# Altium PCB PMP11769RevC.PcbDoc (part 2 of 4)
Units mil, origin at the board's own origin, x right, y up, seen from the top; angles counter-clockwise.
Board outline 7800 x 8510 mil, 4 copper layers (Top, Inner Top, Inner Bottom, Bottom), stack 33.235 mil thick; 451 components, 226 nets, 1199 pads, 1742 vias.
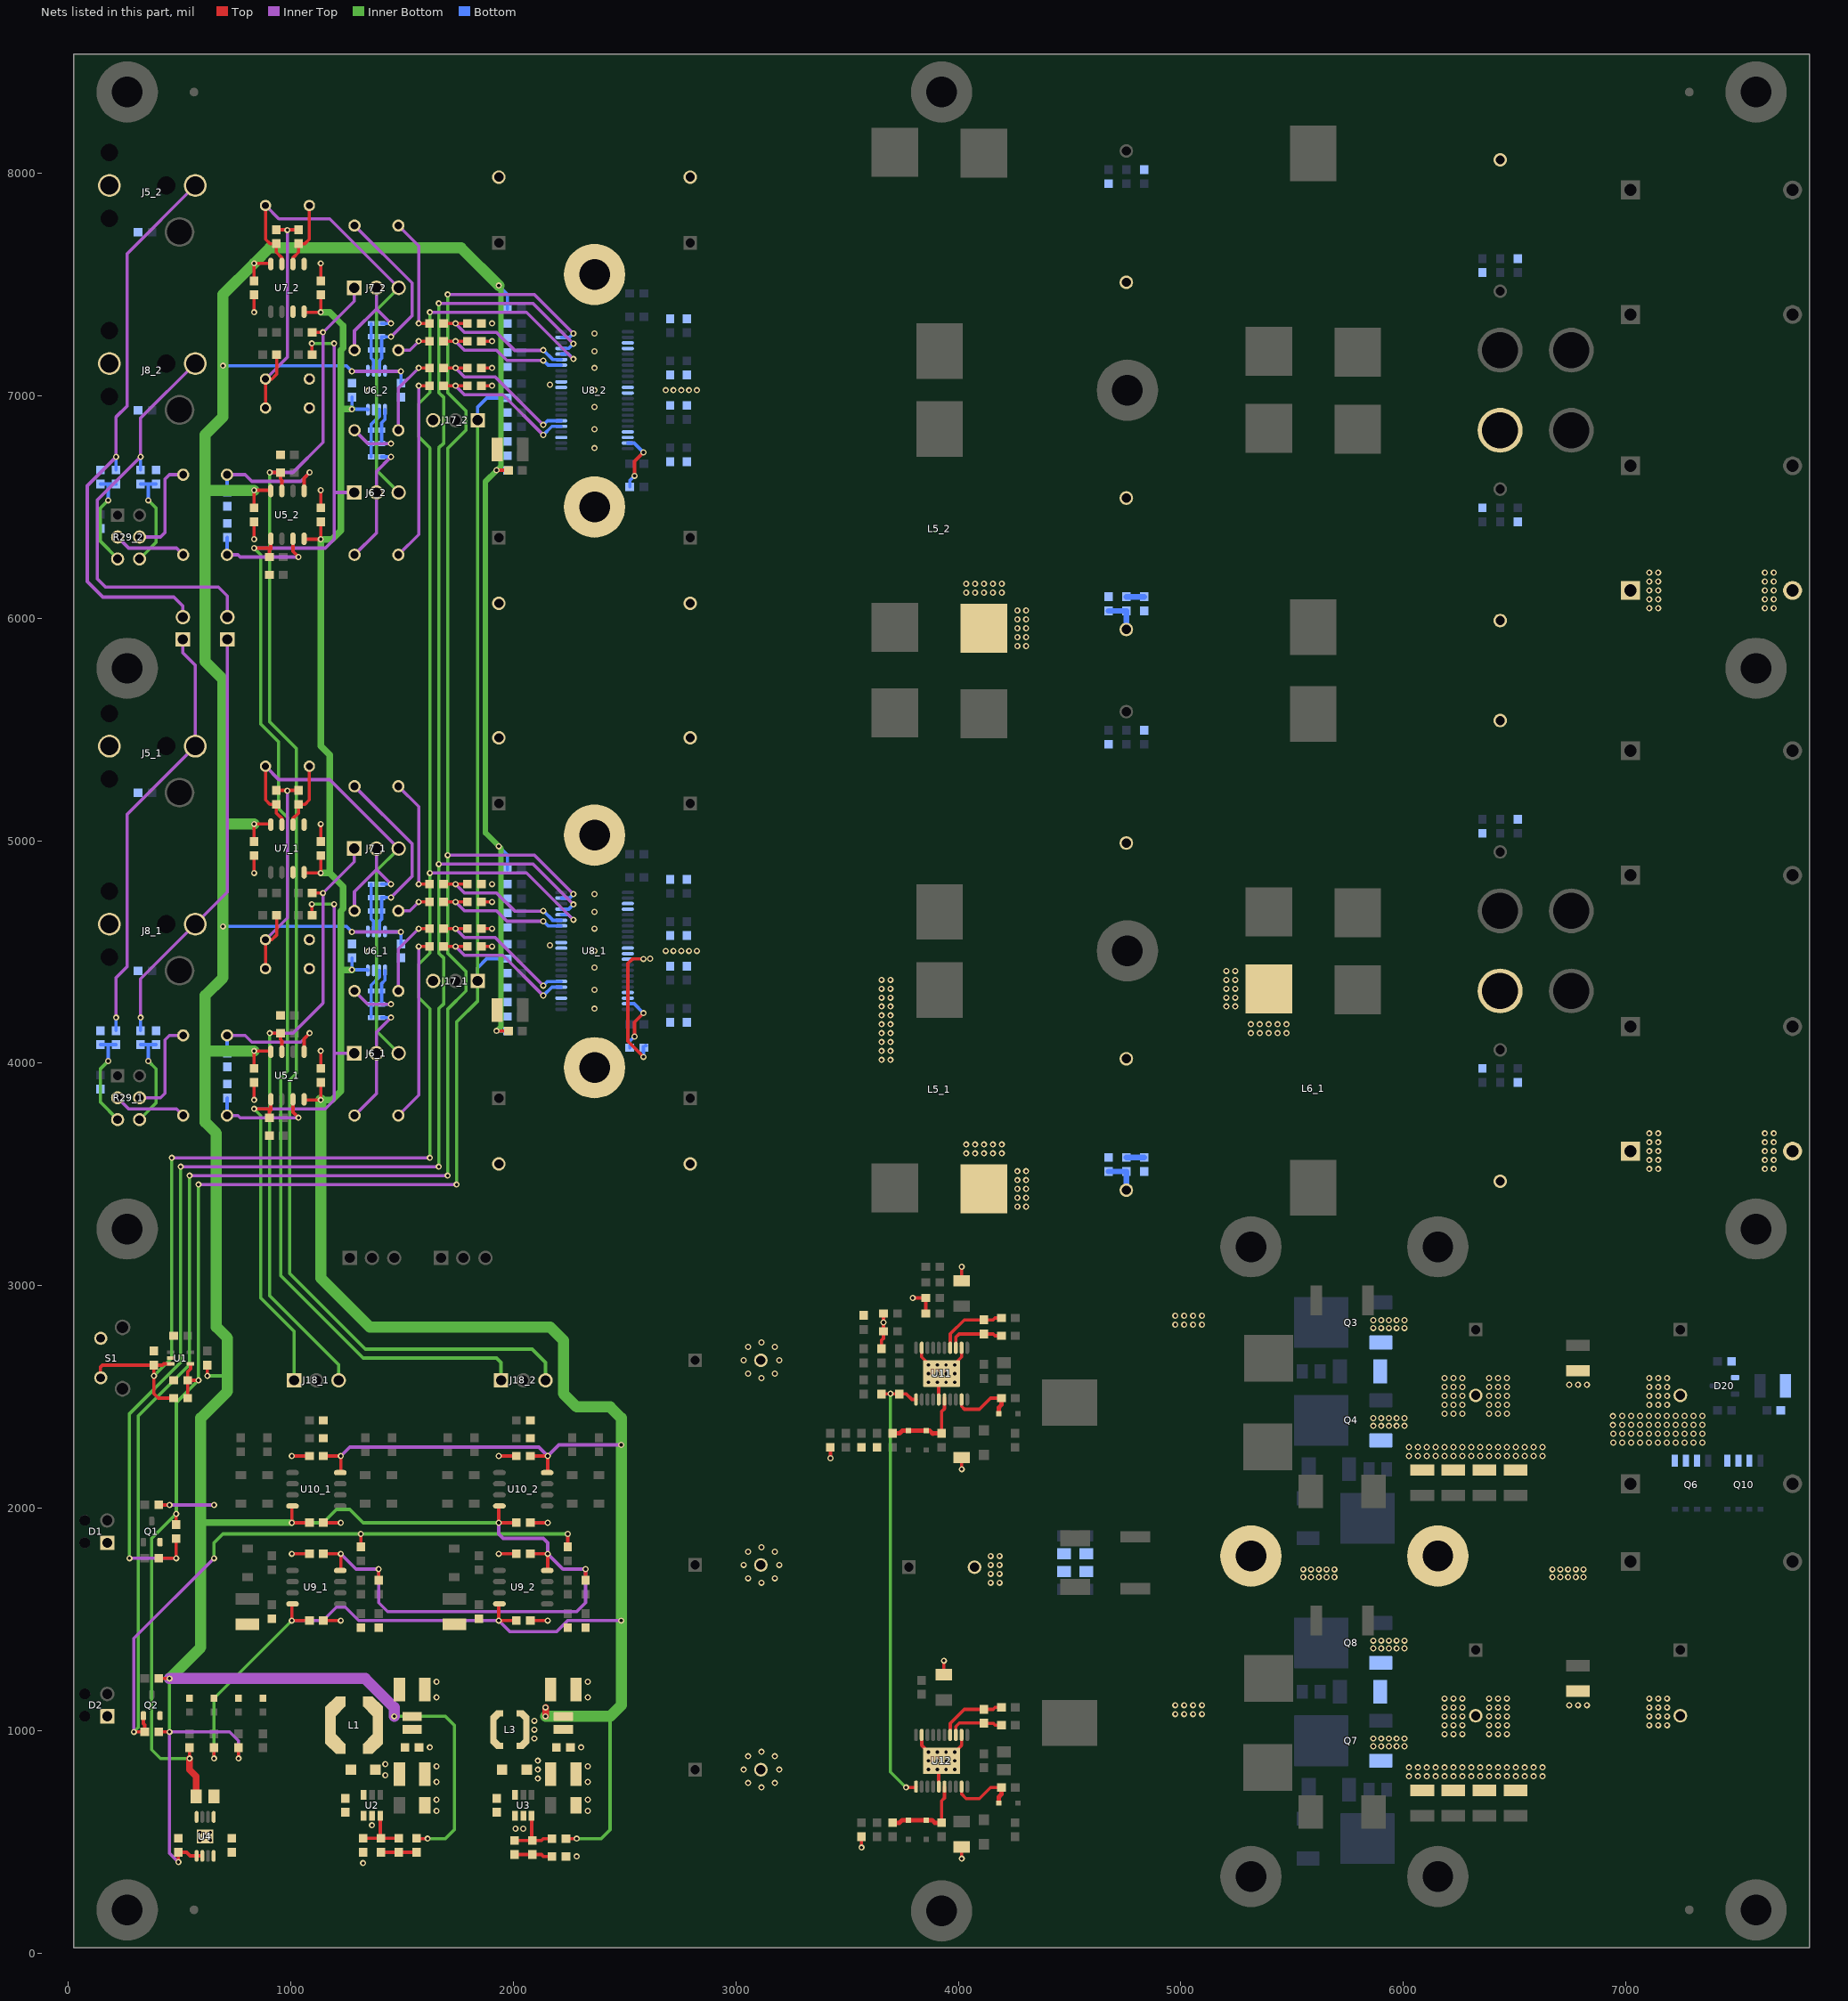
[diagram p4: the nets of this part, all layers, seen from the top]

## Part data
C1 C14 C58_1 C58_2 C59_1 C59_2 C71_1 C71_2: "CAP, CERM, 1 µF, 25 V, +/- 10%, X7R, 0603"
C2 C3 C7 C9 C12 C19_1 C19_2 C23_1 C23_2 C26_1 C26_2 C29_1 C29_2 C30_1 C30_2 C36_1 C36_2 C60_1 C60_2 C66_1 C66_2 C72_1 C72_2 C73_1 C73_2 C77_1 C77_2 C78_1 C78_2 C80_1 C80_2 C81_1 C81_2 C82_1 C82_2 C104 C106: "CAP, CERM, 0.1 µF, 50 V, +/- 10%, X7R, 0603"
C4 C13 C92 C93: "CAP, CERM, 1 µF, 50 V, +/- 10%, X7R, 1206"
C5 C6 C10 C11 C67_1 C67_2 C79_1 C79_2: "CAP, CERM, 10 µF, 25 V, +/- 20%, X7R, 1210"
C8 C17: "CAP, CERM, 220 pF, 50 V, +/- 5%, C0G/NP0, 0603"
C15: "CAP, CERM, 4.7 µF, 10 V, +/- 20%, X7R, 0805"
C16 C90: "CAP, CERM, 1000 pF, 50 V, +/- 10%, X7R, 0603"
C18_1 C18_2 C22_1 C22_2 C25_1 C25_2 C32_1 C32_2 C35_1 C35_2 C39_1 C39_2: "CAP, Film, 4.7 µF, 50 V, +/- 5%, TH"
C20_1 C20_2 C31_1 C31_2: "CAP, CERM, 22 pF, 50 V, +/- 5%, C0G/NP0, 0402"
C21_1 C21_2 C24_1 C24_2 C28_1 C28_2 C37_1 C37_2 C38_1 C38_2 C40_1 C40_2 C91: "CAP, CERM, 100 pF, 50 V, +/- 5%, C0G/NP0, 0603"
C27_1 C27_2: "CAP, Film, 0.1 µF, 63 V, +/- 5%, TH"
C33_1 C33_2: "CAP, Film, 0.22 µF, 63 V, +/- 5%, TH"
C34_1 C34_2: "CAP, Film, 0.15 µF, 63 V, +/- 5%, TH"
C41_1 C41_2 C61_1 C61_2 C68_1 C68_2 C74_1 C74_2: "CAP, CERM, 0.01 µF, 50 V, +/- 10%, X7R, 0603"
C42_1 C42_2 C43_1 C43_2 C44_1 C44_2 C45_1 C45_2 C109 C110 C113 C114: "CAP, AL, 820 µF, 50 V, +/- 20%, 0.042 ohm, TH"
C46_1 C46_2 C47_1 C47_2 C48_1 C48_2 C49_1 C49_2 C50_1 C50_2 C51_1 C51_2 C52_1 C52_2 C53_1 C53_2: "CAP, CERM, 1 µF, 50 V, +/- 10%, X7R, 0603"
C54_1 C54_2 C55_1 C55_2 C64_1 C64_2 C65_1 C65_2: "CAP, CERM, 0.033 µF, 50 V, +/- 10%, X7R, 0603"
C56_1 C56_2 C62_1 C62_2 C69_1 C69_2 C75_1 C75_2: "CAP, Film, 1 µF, 250 V, +/- 5%, TH"
C57_1 C57_2 C63_1 C63_2 C70_1 C70_2 C76_1 C76_2: "CAP, CERM, 1000 pF, 100 V, +/- 5%, C0G/NP0, 0603"
C83 C84: "CAP, CERM, 220 pF, 50 V, +/- 10%, X7R, 0603"
C85: "CAP, CERM, 0.047 µF, 50 V, +/- 10%, X7R, 0603"
C86 C87: "CAP, CERM, 4.7 µF, 16 V, +/- 20%, X7R, 1206"
C88 C89: "CAP, CERM, 0.22 µF, 25 V, +/- 10%, X7R, 0805"
C94: "CAP, CERM, 2.2 µF, 6.3 V, +/- 10%, X7R, AEC-Q200 Grade 1, 0603"
C95 C96 C111 C112 C115 C116: "CAP, CERM, 1000 pF, 100 V, +/- 20%, X7R, 0805"
C97 C99 C100 C102 C103 C105 C117 C119 C120 C122 C123: library part C3225X7R1H335M, "CAP, CERM, 4.7 µF, 50 V, +/- 15%, X7R, 1210"
C98 C101 C118 C121: "CAP, AL, 1800 µF, 35 V, +/- 20%, 0.028 ohm, TH"
C107 C108: "CAP, CERM, 0.1 µF, 100 V, +/- 10%, X7R, 0805"
D1 D2: library part 551-0403F, "LED, Yellow, TH"
D3 D8 D14 D15: library part PMEG6010CEH,115, "Diode, Schottky, 60 V, 1 A, SOD-123F"
D4 D5 D6 D7: "LED, Green, SMD"
D9_1 D9_2 D10_1 D10_2 D11_1 D11_2 D12_1 D12_2 D13_1 D13_2: library part 1N4148WFL-G3-08, "Diode, Switching, 100 V, 0.15 A, SOD-123FL"
D16 D21: library part SS36-E3/57T, "Diode, Schottky, 60 V, 3 A, SMC"
D17 D18 D19 D22 D23 D24: library part BAT54HT1G, "Diode, Schottky, 30 V, 0.2 A, SOD-323"
D20: "Diode, Zener, 15 V, 225 mW, SOT-23"
FID1 FID2 FID3 FID4: "Fiducial mark.  There is nothing to buy or mount."
J1 J3: "Header, 2.54 mm, 2x1, Gold, TH"
J2 J4 J6_1 J6_2 J7_1 J7_2 J17_1 J17_2 J18_1 J18_2: "Header, 2.54 mm, 3x1, Gold, TH"
J5_1 J5_2: "RCA Jack, Red, R/A, TH"
J8_1 J8_2: "RCA Jack, Black, R/A, TH"
J9_1 J9_2 J13_1 J13_2 J19: library part "973 582-101", "TEST SOCKET, PCB, 4MM, RED"
J10_1 J10_2 J11_1 J11_2 J14_1 J14_2 J15_1 J15_2: library part H3492-01, "Pin Receptacle, Dia 4 mm, Gold, TH"
J12_1 J12_2 J16_1 J16_2 J20: library part "973 582-100", "TEST SOCKET, PCB, 4MM, BLACK"
L1: "Inductor, Shielded Drum Core, Ferrite, 330 µH, 0.3 A, 1.2 ohm, SMD"
L2 L4: "Inductor, Shielded, Composite, 500 nH, 2.3 A, 0.04 ohm, SMD"
L3: "Inductor, Shielded Drum Core, Ferrite, 1 mH, 0.1 A, 21.5 ohm, SMD"
L5_1 L5_2 L6_1 L6_2 L7_1 L7_2 L8_1 L8_2 L9 L11: "Inductor, Shielded E Core, Ferrite, 10 µH, 28 A, 0.0026 ohm, SMD"
L10: library part IHLP2525AHERR10M01, "Inductor, Shielded, Ferrite, 100 nH, 18 A, 0.0035 ohm, SMD"
Q1 Q2: library part 2N7002E-T1-E3, "MOSFET, N-CH, 60 V, 0.24 A, SOT-23"
Q3 Q4 Q5 Q7 Q8 Q9: library part SUD50N10-18P, "MOSFET, N-CH, 60 V, 50 A, DPAK"
Q6 Q10: "MOSFET, N-CH, 30 V, 51 A, SON 5x6mm"
R1 R7: "RES, 47.5 k, 1%, 0.1 W, 0603"
R2 R8: "RES, 3.32 k, 1%, 0.1 W, 0603"
R3 R6 R25_1 R25_2 R30_1 R30_2 R43_1 R43_2 R53_1 R53_2 R55_1 R55_2 R56_1 R56_2 R59_1 R59_2 R61_1 R61_2 R63_1 R63_2 R64_1 R64_2 R65_1 R65_2 R66_1 R66_2: "RES, 10.0 k, 1%, 0.1 W, 0603"
R4 R19_1 R19_2 R20_1 R20_2 R26_1 R26_2 R36_1 R36_2 R37_1 R37_2 R42_1 R42_2: "RES, 100, 1%, 0.1 W, 0603"
R5: "RES, 80.6 k, 1%, 0.1 W, 0603"
R9 R17 R77: "RES, 49.9, 1%, 0.1 W, 0603"
R10 R16 R58_1 R58_2 R89 R91 R92 R100 R101: "RES, 1.00 k, 1%, 0.1 W, 0603"
R11 R18: "RES, 14.7 k, 1%, 0.1 W, 0603"
R12: "RES, 11.0 k, 1%, 0.1 W, 0603"
R13 R14: "RES, 2.94 k, 1%, 0.1 W, 0603"
R15: "RES, 200, 1%, 0.1 W, 0603"
R21_1 R21_2 R27_1 R27_2 R38_1 R38_2 R39_1 R39_2: "RES, 10.0 k, 1%, 0.063 W, 0402"
R22_1 R22_2: "RES, 13.7 k, 1%, 0.1 W, 0603"
R23_1 R23_2 R32_1 R32_2 R40_1 R40_2 R54_1 R54_2 R67 R70 R72 R73 R75 R76 R79 R83: "RES, 0, 5%, 0.1 W, 0603"
R24_1 R24_2 R41_1 R41_2 R74 R78: "RES, 100 k, 1%, 0.1 W, 0603"
R28_1 R28_2 R33_1 R33_2 R81 R84: "RES, 20.0 k, 1%, 0.1 W, 0603"
R29_1 R29_2: "Trimmer Potentiometer, 10K Ohm, 0.025W, TH"
R31_1 R31_2 R44_1 R44_2: "RES, 24.3 k, 1%, 0.1 W, 0603"
R34_1 R34_2: "RES, 4.53 k, 1%, 0.1 W, 0603"
R35_1 R35_2: "RES, 6.81 k, 1%, 0.1 W, 0603"
R45_1 R45_2 R46_1 R46_2 R47_1 R47_2 R48_1 R48_2 R50_1 R50_2 R51_1 R51_2 R52_1 R52_2 R69 R71: "RES, 3.32, 1%, 0.1 W, 0603"
R49_1 R49_2: "RES, 22.1 k, 1%, 0.1 W, 0603"
R57_1 R57_2: "RES, 23.7 k, 1%, 0.1 W, 0603"
R60_1 R60_2: "RES, 200 k, 1%, 0.1 W, 0603"
R62_1 R62_2: "RES, 365 k, 1%, 0.1 W, 0603"
R68: "RES, 30.1 k, 1%, 0.1 W, 0603"
R80: "RES, 7.68 k, 1%, 0.1 W, 0603"
R82: "RES, 37.4 k, 1%, 0.1 W, 0603"
R85: "RES, 3.74 k, 1%, 0.1 W, 0603"
R86: "RES, 44.2 k, 1%, 0.1 W, 0603"
R87 R90 R97 R99: "RES, 8.2, 5%, 0.75 W, 2010"
R88 R98: "RES, 0.0015, 1%, 1 W, 2512"
R93 R94 R95 R102 R103 R104: "RES, 4.75, 1%, 0.1 W, 0603"
R96: "RES, 0.68, 5%, 1 W, 2512"
S1: library part 1825027-2, "Switch, SPST-NO, Off-Mom, 0.05 A, 12 V, R/A, TH"
U1: library part TPS3803-01QDCKRQ1, "VOLTAGE DETECTOR, DCK0005A"
U2 U3: library part LM2841XMK-ADJL, "300 mA/600 mA up to 42V Input Step-Down DC/DC Regulator, 6-pin Tiny SOT23"
U4: library part TPS7A6633QDGNRQ1, "High-Voltage Ultralow-Iq Low-Dropout Regulator, DGN0008D"
U5_1 U5_2 U7_1 U7_2: library part OPA1662AIDRQ1, "Automotive Catalog, Sound Plus, Low-Power, Low-Noise and Distortion, Audio Operational Amplifier, 3 to 36 V, -40 to 85 degC, 8-pin SOIC (D0008A), Green (RoHS & no Sb/Br)"
U6_1 U6_2: "Automotive Catalog, Sound Plus, Low-Power, Low-Noise and Distortion, Audio Operational Amplifier, 3 to 36 V, -40 to 85 degC, 8-pin SOP (DGK0008A), Green (RoHS & no Sb/Br)"
U8_1 U8_2: library part TPA3251D2DDVR, "150W Stereo/300W MONO PurePath HD Analog-input Power Stage, DDV0044D"
U9_1 U9_2 U10_1 U10_2: library part LM2904QDRQ1, "Automotive Dual Low Power Op Amp, D0008A"
U11 U12: library part LM5122QMHX/NOPB, "Wide Input Synchronous Boost Controller with Multiple Phase Capability, PWP0020A"

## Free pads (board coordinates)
  round 275.59 hole 137.8 unplated: 0(265,195) 0(265,3255) 0(265,5775) 0(265,8365) 0(3925,190) 0(3925,8365) 0(4760,4505) 0(4760,7025) 0(5315,345) 0(5315,3175) 0(6155,345) 0(6155,3175) 0(7585,195) 0(7585,3255) 0(7585,5775) 0(7585,8365)
  round 275.59 hole 137.8: 0(2365,3980) 0(2365,5025) 0(2365,6500) 0(2365,7545) 0(5315,1785) 0(6155,1785)

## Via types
v1: diameter 28, hole 15, Top to Bottom, 1742 vias

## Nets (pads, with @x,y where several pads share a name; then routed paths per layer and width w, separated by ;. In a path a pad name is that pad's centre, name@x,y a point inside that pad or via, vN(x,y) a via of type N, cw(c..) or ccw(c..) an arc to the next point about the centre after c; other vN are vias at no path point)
+3V3: C2.2 C15.1 J17_1.1 J17_2.1 R1.2 R3.2 R15.2 R54_1.1 R54_2.1 U1.4 U4.8 | length 8355.1
  Top w15: R1.2@485,1926.5 v1(485,1975) ; R3.2@536.5,2495 C2.2@536.5,2575 ; v1(545,875) R15.2@545,923.5 ; U1.4@549.29,2649.41 549.29,2626.14 536.5,2613.35 C2.2@536.5,2575 ; v1(585,2575) C2.2@536.5,2575
  Top w30: v1(545,875) 545,825 575,795 C15.1@575,705
  Inner Top w15: v1(585,3455) v1(1745,3455)
  Inner Bottom w15: v1(545,875) 415,875 375,915 375,1865 v1(485,1975) 485.37,1975.37 485.37,2475.37 v1(585,2575) v1(585,3455) ; v1(1745,3455) 1745,4185 1840,4280 J17_1.1@1840,4370 J17_2.1@1840,6890
  Bottom w15: J17_1.1@1840,4370 1840,4429.49 1880.51,4470 R54_1.1@1973.5,4470 ; J17_2.1@1840,6890 1840,6949.49 1880.51,6990 R54_2.1@1973.5,6990
+12V: C6.1 C14.1 C23_1.1 C23_2.1 C26_1.1 C26_2.1 C29_1.1 C29_2.1 C77_1.1 C77_2.1 C78_1.1 C78_2.1 L2.2 R2.2 R5.2 R7.2 R8.2 R9.2 R13.2 R46_1.2 R46_2.2 R48_1.2 R48_2.2 R51_1.2 R51_2.2 R57_1.2 R57_2.2 U4.1 U4.2 U5_1.8 U5_2.8 U6_1.8 U6_2.8 U7_1.8 U7_2.8 U9_1.8 U9_2.8 U10_1.8 U10_2.8 | length 22962.4
  Top w15: R7.2@406.5,995 v1(455,995) ; R8.2@406.5,1235 v1(455,1235) ; R2.2@406.5,2015 v1(455,2015) ; v1(495,410) C14.1@495,453.5 531.5,453.5 547.6,437.4 U4.1@576.61,437.4 U4.2@602.2,437.4 ; v1(625,2595) R5.2@625,2643.5 ; v1(765,875) R13.2@765,923.5 ; C26_1.1@835,3976.5 v1(835,4055) 907.28,4055 U5_1.8@910,4052.28 ; C29_1.1@835,4996.5 v1(835,5075) 907.28,5075 U7_1.8@910,5072.28 ; C26_2.1@835,6496.5 v1(835,6575) 907.28,6575 U5_2.8@910,6572.28 ; C29_2.1@835,7516.5 v1(835,7595) 907.28,7595 U7_2.8@910,7592.28 ; U10_1.8@1007.72,2010 1005,2007.28 v1(1005,1935) C78_1.1@1083.5,1935 ; C77_1.1@1146.5,1795 v1(1225,1795) 1225,1722.72 U9_1.8@1222.28,1720 ; R57_1.2@1395,1676.5 v1(1395,1726.67) ; R9.2@1565,516.5 1566.5,515 v1(1615,515) ; v1(1925,4145) R48_1.2@1978.5,4145 ; v1(1925,6665) R48_2.2@1978.5,6665 ; U10_2.8@1937.72,2010 1935,2007.28 v1(1935,1935) C78_2.1@2013.5,1935 ; C77_2.1@2076.5,1795 v1(2155,1795) 2155,1722.72 U9_2.8@2152.28,1720 ; R57_2.2@2325,1676.5 v1(2325,1726.67)
  Inner Top w15: v1(455,2015) v1(655,2015) ; v1(495,410) 455,450 v1(455,995) 725,995 765,955 v1(765,875) ; v1(1225,1795) 1293.33,1726.67 v1(1395,1726.67) 1395,1575 1435,1535 2285,1535 2325,1575 v1(2325,1726.67) 2223.33,1726.67 v1(2155,1795) 2155,1845 2135,1865 1955,1865 1935,1885 v1(1935,1935) ; v1(1275,4590) v1(1495,4590) ; v1(1275,7110) v1(1495,7110)
  Inner Top w50: v1(455,1235) 1335,1235 1465,1105 v1(1465,1065)
  Inner Bottom w15: v1(455,995) v1(455,1235) ; 595,2015 v1(655,2015) ; v1(625,2595) 705,2595 715,2605 ; v1(1005,1935) 1145,1935 1205,1995 1265,1995 1325,1935 v1(1935,1935) ; v1(1465,1065) 1695,1065 1735,1025 1735,555 1695,515 v1(1615,515)
  Inner Bottom w25: v1(1925,4145) 1945.02,4165.02 1945.02,4964.98 v1(1935,4975) 1875,5035 1874.63,5035 1874.63,6614.63 v1(1925,6665) 1945.02,6685.02 1945.02,7484.98 v1(1935,7495)
  Inner Bottom w30: 595,1935 v1(1005,1935)
  Inner Bottom w50: v1(455,1235) 595,1375 595,1935 595,2015 595,2405 715,2525 715,2605 715,2765 665,2815 665,3685 615,3735 615,4055 ; v1(835,4055) 615,4055 ; v1(835,5075) 695,5075 ; v1(835,6575) 615,6575 ; v1(1935,7495) 1765,7665 905,7665 v1(835,7595) 695,7455 v1(695,7135) 695,6905 615,6825 615,6575 ; 615,4055 615,4305 695,4385 695,5075 ; 615,6575 615,5805 695,5725 695,5075
  Bottom w15: v1(695,4615) 1250,4615 v1(1275,4590) ; v1(695,7135) 1250,7135 v1(1275,7110) ; U6_1.8@1423.39,4592.6 1425.98,4590 v1(1495,4590) C23_1.1@1495,4536.5 ; U6_2.8@1423.39,7112.6 1425.98,7110 v1(1495,7110) C23_2.1@1495,7056.5 ; v1(1925,4145) R46_1.2@1973.5,4145 ; v1(1925,6665) R46_2.2@1973.5,6665 ; v1(1935,4975) 1973.5,4936.5 R51_1.2@1973.5,4870 ; v1(1935,7495) 1973.5,7456.5 R51_2.2@1973.5,7390
-12V: C11.2 C19_1.1 C19_2.1 C30_1.1 C30_2.1 C36_1.1 C36_2.1 C80_1.1 C80_2.1 C82_1.1 C82_2.1 L4.2 R14.2 R16.2 U5_1.4 U5_2.4 U6_1.4 U6_2.4 U7_1.4 U7_2.4 U9_1.4 U9_2.4 U10_1.4 U10_2.4 | length 14081.9
  Top w15: v1(655,875) R14.2@655,923.5 ; U9_1.4@1007.72,1570 1005,1567.28 v1(1005,1495) C80_1.1@1083.5,1495 ; U5_1.4@1060,3837.72 1062.72,3835 v1(1135,3835) C19_1.1@1135,3913.5 ; U7_1.4@1060,4857.72 1062.72,4855 v1(1135,4855) C36_1.1@1135,4933.5 ; U5_2.4@1060,6357.72 1062.72,6355 v1(1135,6355) C19_2.1@1135,6433.5 ; U7_2.4@1060,7377.72 1062.72,7375 v1(1135,7375) C36_2.1@1135,7453.5 ; C82_1.1@1146.5,2235 v1(1225,2235) 1225,2162.72 U10_1.4@1222.28,2160 ; U9_2.4@1937.72,1570 1935,1567.28 v1(1935,1495) C80_2.1@2013.5,1495 ; C82_2.1@2076.5,2235 v1(2155,2235) 2155,2162.72 U10_2.4@2152.28,2160 ; R16.2@2236.5,515 v1(2285,515)
  Top w30: v1(2145,1065) v1(2145,1105)
  Inner Top w15: v1(1005,1495) 1145,1495 1205,1555 1245,1555 1305,1495 v1(1935,1495) 1985,1445 2195,1445 2245,1495 v1(2485,1495) ; v1(1225,2235) 1265,2275 2115,2275 v1(2155,2235) 2205,2285 v1(2485,2285)
  Inner Bottom w15: v1(655,875) 655,1145 v1(1005,1495) ; v1(2285,515) 2395,515 2435,555 2435,1060 2430,1065
  Inner Bottom w30: v1(1135,3835) 1185,3835 1225,3875 1225,4420 ; v1(1135,4855) 1175,4855 ; v1(1135,7375) 1175,7375 1236.14,7313.86 1236.14,7215 1225,7203.86 1225,6940 ; v1(1275,4420) 1225,4420 ; v1(1275,6940) 1225,6940 ; 1175,4855 1236.14,4793.86 1236.14,4695 1225,4683.86 1225,4420 ; 1175,4855 1175,5385 1135,5425 v1(1135,6355) 1185,6355 1225,6395 1225,6940
  Inner Bottom w50: v1(1135,3835) 1135,3035 1355,2815 2165,2815 2225,2755 2225,2515 2285,2455 2435,2455 2485,2405 v1(2485,2285) v1(2485,1495) 2485,1115 2435,1065 ; v1(2145,1065) 2430,1065
  Bottom w15: C30_1.1@1275,4473.5 v1(1275,4420) 1344.02,4420 U6_1.4@1346.61,4417.4 ; C30_2.1@1275,6993.5 v1(1275,6940) 1344.02,6940 U6_2.4@1346.61,6937.4
/CLIP_1: Q2.1 R7.1 R58_1.2 R58_2.2 U8_1.21 U8_2.21 | length 12109.8
  Top w15: v1(295,995) R7.1@343.5,995 343.5,1026.5 337.6,1032.4 Q2.1@337.6,1067.76 Q2.1@334.84,1065 ; R58_1.2@1315,1826.5 v1(1315,1885) ; R58_2.2@2245,1826.5 v1(2245,1885)
  Inner Top w15: v1(295,995) 295,1415 v1(655,1775) ; v1(545,3495) v1(1705,3495) ; v1(1705,4935) 2095,4935 v1(2270,4760) ; v1(1705,7455) 2095,7455 v1(2270,7280)
  Inner Bottom w15: v1(295,995) 315,1015 315,2415 545,2645 v1(545,3495) ; v1(655,1775) 655,1845 695,1885 v1(1315,1885) v1(2245,1885) ; v1(1705,3495) 1705,4242.15 1787.85,4325 1787.85,4412.15 1705,4495 v1(1705,4935) 1705,6762.15 1787.85,6845 1787.85,6932.15 1705,7015 v1(1705,7455)
  Bottom w15: U8_1.21@2215.39,4742.5 2252.5,4742.5 v1(2270,4760) ; U8_2.21@2215.39,7262.5 2252.5,7262.5 v1(2270,7280)
/FAULT_1: R1.1 R4.1 U8_1.19 U8_2.19 | length 8797.1
  Top w15: R4.1@406.5,1775 v1(485,1775) R1.1@485,1863.5
  Inner Top w15: v1(275,1775) v1(485,1775) ; v1(505,3535) v1(1665,3535) ; v1(1665,4895) 2088.7,4895 v1(2270,4713.7) ; v1(1665,7415) 2088.7,7415 v1(2270,7233.7)
  Inner Bottom w15: v1(275,1775) 275,2425 505,2655 v1(505,3535) ; v1(1665,3535) 1665,4245 1687.85,4267.85 1687.85,4472.15 1665,4495 v1(1665,4895) 1665,6765 1687.85,6787.85 1687.85,6992.15 1665,7015 v1(1665,7415)
  Bottom w15: U8_1.19@2215.39,4692.5 2248.8,4692.5 v1(2270,4713.7) ; U8_2.19@2215.39,7212.5 2248.8,7212.5 v1(2270,7233.7)
/RESET_1: C1.1 R3.1 S1.2 U1.3 U8_1.18 U8_2.18 | length 8243.8
  Top w15: S1.2@145.98,2586.42 145,2587.4 145,2635 153.5,2643.5 C1.1@385,2643.5 ; U1.3@460.71,2649.41 429.41,2649.41 423.5,2643.5 C1.1@385,2643.5 ; R3.1@473.5,2495 405,2495 385,2515 v1(385,2595) C1.1@385,2643.5
  Inner Top w15: v1(465,3575) v1(1625,3575) ; v1(1625,4855) 2060,4855 v1(2270,4645) ; v1(1625,7375) 2060,7375 v1(2270,7165)
  Inner Bottom w15: v1(385,2595) 465,2675 v1(465,3575) ; v1(1625,3575) 1625,4245 1575,4295 1575,4445 1625,4495 v1(1625,4855) 1625,6765 1575,6815 1575,6965 1625,7015 v1(1625,7375)
  Bottom w15: U8_1.18@2215.39,4667.5 2247.5,4667.5 v1(2270,4645) ; U8_2.18@2215.39,7187.5 2247.5,7187.5 v1(2270,7165)
BUFF_L1: J6_1.1 J18_1.1 R28_1.1 R31_1.2 U5_1.1 | length 2958.1
  Top w15: v1(835,3795) 905,3795 910,3790 ; R31_1.2@903.5,3755 903.5,3783.5 910,3790 ; U5_1.1@907.28,3835 U5_1.1@910,3837.72 910,3790 ; v1(1095,4715) 1095,4666.5 R28_1.1@1096.5,4665
  Inner Top w15: v1(835,3795) 1155,3795 1195,3835 1195,4045 ; v1(1195,4715) 1195,4045 ; J6_1.1@1285,4045 1195,4045
  Inner Bottom w15: v1(835,3795) 865,3765 865,2945 1015,2795 J18_1.1@1015,2575 ; v1(1095,4715) v1(1195,4715)
BUFF_L2: J6_2.1 J18_2.1 R28_2.1 R31_2.2 U5_2.1 | length 6239.6
  Top w15: v1(835,6315) 905,6315 910,6310 ; R31_2.2@903.5,6275 903.5,6303.5 910,6310 ; U5_2.1@907.28,6355 U5_2.1@910,6357.72 910,6310 ; v1(1095,7235) 1095,7186.5 R28_2.1@1096.5,7185
  Inner Top w15: v1(835,6315) 1155,6315 1195,6355 1195,6565 ; v1(1195,7235) 1195,6565 ; J6_2.1@1285,6565 1195,6565
  Inner Bottom w15: v1(835,6315) 865,6285 865,5525 945,5445 945,5145 985,5105 985,3965 955,3935 955,3045 1325,2675 1925,2675 1945,2655 J18_2.1@1945,2575 ; v1(1095,7235) v1(1195,7235)
BUFF_R1: J7_1.1 J18_1.3 R33_1.1 R44_1.2 U5_1.7 | length 2919.4
  Top w15: v1(905,4135) R44_1.2@953.5,4135 953.5,4106.5 960,4100 U5_1.7@960,4052.28 ; R33_1.1@1096.5,4765 v1(1145,4765)
  Inner Top w15: v1(905,4135) 1009.45,4135 1145,4270.55 v1(1145,4765) 1285,4905 J7_1.1@1285,4965
  Inner Bottom w15: v1(905,4135) 905,2955 1215,2645 J18_1.3@1215,2575
BUFF_R2: J7_2.1 J18_2.3 R33_2.1 R44_2.2 U5_2.7 | length 6288.8
  Top w15: v1(905,6655) R44_2.2@953.5,6655 953.5,6626.5 960,6620 U5_2.7@960,6572.28 ; R33_2.1@1096.5,7285 v1(1145,7285)
  Inner Top w15: v1(905,6655) 1009.45,6655 1145,6790.55 v1(1145,7285) 1285,7425 J7_2.1@1285,7485
  Inner Bottom w15: v1(905,6655) 905,5535 1025,5415 1025,3955 995,3925 995,3055 1335,2715 2085,2715 2145,2655 J18_2.3@2145,2575
COMP: C85.1 C90.1 U11.11 U12.11 | length 2010.5
  Top w15: C90.1@3655,2513.5 C85.1@3735,2513.5 3766.5,2513.5 3791.14,2488.86 U11.11@3809.84,2488.86 ; v1(3765,745) 3805.98,745 U12.11@3809.84,748.86
  Inner Bottom w15: v1(3695,2515) 3695,815 v1(3765,745)
CSN-1: C83.2 R92.1 U11.3 | length 262.2
  Top w15: U11.3@3988.98,2721.14 3988.98,2768.35 3988.66,2768.66 4003.5,2783.5 C83.2@4115,2783.5 4156.5,2783.5 4165,2775 R92.1@4193.5,2775
CSN-2: C84.2 R101.1 U12.3 | length 253.1
  Top w15: U12.3@3988.98,981.14 3988.98,1018.98 4005,1035 4113.5,1035 C84.2@4115,1033.5 4156.5,1033.5 4165,1025 R101.1@4193.5,1025
CSP-1: C83.1 R91.1 U11.4 | length 322.3
  Top w15: U11.4@3963.39,2721.14 3963.39,2782.76 3963.07,2783.07 4026.5,2846.5 C83.1@4115,2846.5 4156.5,2846.5 4165,2855 R91.1@4193.5,2855
CSP-2: C84.1 R100.1 U12.4 | length 312
  Top w15: U12.4@3963.39,981.14 3963.39,1033.39 4026.5,1096.5 C84.1@4115,1096.5 4156.5,1096.5 4165,1105 R100.1@4193.5,1105
GND: C1.2 C2.1 C4.2 C5.2 C6.2 C7.1 C10.1 C11.1 C12.2 C13.2 C14.2 C15.2 C16.2 C19_1.2 C19_2.2 C21_1.2 C21_2.2 C23_1.2 C23_2.2 C24_1.2 C24_2.2 C26_1.2 C26_2.2 C28_1.2 C28_2.2 C29_1.2 C29_2.2 C30_1.2 C30_2.2 C33_1.2 C33_2.2 C34_1.2 C34_2.2 C36_1.2 C36_2.2 C37_1.2 C37_2.2 C38_1.2 C38_2.2 C40_1.2 C40_2.2 C42_1.2 C42_2.2 C43_1.2 C43_2.2 C44_1.2 C44_2.2 C45_1.2 C45_2.2 C46_1.2 C46_2.2 C47_1.2 C47_2.2 C48_1.2 C48_2.2 C49_1.2 C49_2.2 C50_1.2 C50_2.2 C51_1.2 C51_2.2 C52_1.2 C52_2.2 C53_1.2 C53_2.2 C56_1.2 C56_2.2 C57_1.2 C57_2.2 C58_1.2 C58_2.2 C59_1.2 C59_2.2 C60_1.1 C60_2.1 C62_1.2 C62_2.2 C63_1.2 C63_2.2 C66_1.1 C66_2.1 C67_1.2 C67_2.2 C69_1.2 C69_2.2 C70_1.2 C70_2.2 C71_1.1 C71_2.1 C72_1.1 C72_2.1 C73_1.2 C73_2.2 C75_1.2 C75_2.2 C76_1.2 C76_2.2 C77_1.2 C77_2.2 C78_1.2 C78_2.2 C79_1.2 C79_2.2 C80_1.2 C80_2.2 C81_1.1 C81_2.1 C82_1.2 C82_2.2 C86.2 C87.2 C91.2 C92.1 C93.1 C94.2 C97.2 C98.2 C99.2 C100.2 C101.2 C102.2 C103.2 C104.2 C105.2 C106.1 C107.1 C108.2 C109.2 C110.2 C112.2 C113.2 C114.2 C115.1 C117.2 C118.2 C119.2 C120.2 C121.2 C122.2 C123.2 D1.1 D2.1 D3.2 D4.1 D5.1 D6.2 D7.1 D20.1 J5_1.1 J5_2.1 J8_1.1 J8_2.1 J17_1.3 J17_2.3 L3.2 pad.0@2365,3980 pad.0@2365,5025 pad.0@2365,6500 pad.0@2365,7545 pad.0@5315,1785 pad.0@6155,1785 Q1.2 Q2.2 Q3.3 Q4.3 Q6.1 Q6.2 Q6.3 Q7.3 Q8.3 Q10.1 Q10.2 Q10.3 R6.1 R10.1 R17.1 R23_1.1 R23_2.1 R24_1.1 R24_2.1 R30_1.2 R30_2.2 R32_1.1 R32_2.1 R40_1.1 R40_2.1 R41_1.1 R41_2.1 R43_1.2 R43_2.2 R45_1.1 R45_2.1 R47_1.1 R47_2.1 R49_1.1 R49_2.1 R50_1.1 R50_2.1 R52_1.1 R52_2.1 R53_1.1 R53_2.1 R60_1.1 R60_2.1 R61_1.2 R61_2.2 R65_1.1 R65_2.1 R66_1.1 R66_2.1 R79.2 R80.1 R81.1 R82.1 R83.1 R84.1 R85.1 R86.1 R90.1 R99.1 S1.1 U1.2 U2.2 U4.5 U4.9 U6_1.3 U6_1.5 U6_2.3 U6_2.5 U7_1.3 U7_1.5 U7_2.3 U7_2.5 U8_1.3 U8_1.12 U8_1.13 U8_1.25 U8_1.26 U8_1.33 U8_1.34 U8_1.41 U8_1.42 U8_2.3 U8_2.12 U8_2.13 U8_2.25 U8_2.26 U8_2.33 U8_2.34 U8_2.41 U8_2.42 U11.2 U11.9 U11.15 U11.21 U12.2 U12.9 U12.15 U12.21 | length 3077.5
  Top w15: v1(835,3835) C26_1.2@835,3913.5 ; v1(835,4855) C29_1.2@835,4933.5 ; v1(835,6355) C26_2.2@835,6433.5 ; v1(835,7375) C29_2.2@835,7453.5 ; v1(1005,1795) C77_1.2@1083.5,1795 ; v1(1005,2235) C82_1.2@1083.5,2235 ; C19_1.2@1135,3976.5 v1(1135,4055) ; C36_1.2@1135,4996.5 v1(1135,5075) ; C19_2.2@1135,6496.5 v1(1135,6575) ; C36_2.2@1135,7516.5 v1(1135,7595) ; C80_1.2@1146.5,1495 v1(1225,1495) ; C78_1.2@1146.5,1935 v1(1225,1935) ; C21_1.2@1856.5,4523.7 1857.8,4525 v1(1905,4525) ; C28_1.2@1856.5,4603.7 1857.8,4605 v1(1905,4605) ; C40_1.2@1856.5,4723.7 1857.8,4725 v1(1905,4725) ; C21_2.2@1856.5,7043.7 1857.8,7045 v1(1905,7045) ; C28_2.2@1856.5,7123.7 1857.8,7125 v1(1905,7125) ; C40_2.2@1856.5,7243.7 1857.8,7245 v1(1905,7245) ; v1(1935,1795) C77_2.2@2013.5,1795 ; v1(1935,2235) C82_2.2@2013.5,2235 ; C80_2.2@2076.5,1495 v1(2155,1495) ; C78_2.2@2076.5,1935 v1(2155,1935) ; v1@3425,2226.5 R81.1@3425,2275 ; v1(3565,475) R84.1@3565,523.5 ; R85.1@3655,2716.5 3655,2755 3663.5,2763.5 v1(3663.5,2835) C94.2@3663.5,2875 ; v1(3795,2945) R80.1@3853.5,2945 C91.2@3853.5,2875 ; U11.9@3835.12,2730.51 3835,2730.39 3835,2680 3900.63,2614.37 U11.21@3924.68,2614.37 ; U12.9@3835.43,981.14 3835.43,934.57 3905,865 v1(3905.32,865) U12.21@3925,865 ; U11.15@3911.89,2498.23 3911.89,2601.57 U11.21@3924.68,2614.37 ; U12.15@3912.2,748.86 3912.2,852.2 U12.21@3925,865 ; C93.1@3935,1252.09 v1(3935,1315) ; U11.2@4014.25,2730.51 4015,2729.76 4015,2680 3949.37,2614.37 U11.21@3924.68,2614.37 ; U12.2@4014.57,981.14 4014.57,934.57 3945,865 v1(3944.69,865) U12.21@3925,865 ; v1(4015,425) C87.2@4015,477.91 ; v1(4015,2175.55) C86.2@4015,2227.91 ; C92.1@4015,3022.09 v1(4015,3085)
  other v1: 1325,405 2285,435 591.38,507.28 638.62,507.28 615,525 591.38,542.72 638.62,542.72 1365,575 1655,640 2335,640 1655,690 2335,690 3115,745 3055,765 3175,765 1655,770 2335,770 6025,795 6065,795 6105,795 6145,795 6185,795 6225,795 6265,795 6305,795 6345,795 6385,795 6425,795 6465,795 6505,795 6545,795 6585,795 6625,795 1425,800 3035,825 3195,825 3865.94,825.63 3905.32,825.63 3944.69,825.63 3984.06,825.63 6025,835 6065,835 6105,835 6145,835 6185,835 6225,835 6265,835 6305,835 6345,835 6385,835 6425,835 6465,835 6505,835 6545,835 6585,835 6625,835 1655,840 2335,840 1425,850 3865.94,865 3984.06,865 3055,885 3175,885 3865.94,904.37 3905.32,904.37 3944.69,904.37 3984.06,904.37 3115,905 1625,925 2305,925 5865,930 5900,930 5935,930 5970,930 6005,930 2095,965 5865,965 5900,965 5935,965 5970,965 6005,965 6185,985 6225,985 6265,985 6385,985 6425,985 6465,985 2095,1005 6185,1025 6225,1025 6265,1025 6385,1025 6425,1025 6465,1025 7105,1025 7145,1025 7185,1025 2095,1045 6185,1065 6225,1065 6265,1065 6385,1065 6425,1065 6465,1065 7105,1065 7145,1065 7185,1065 4975,1075 5015,1075 5055,1075 5095,1075 6185,1105 6225,1105 6265,1105 6385,1105 6425,1105 6465,1105 7105,1105 7145,1105 7185,1105 4975,1115 5015,1115 5055,1115 5095,1115 6745,1115 6785,1115 6825,1115 6185,1145 6225,1145 6265,1145 6385,1145 6425,1145 6465,1145 7105,1145 7145,1145 7185,1145 1655,1150 2335,1150 1655,1220 2335,1220 5865,1370 5900,1370 5935,1370 5970,1370 6005,1370 5865,1405 5900,1405 5935,1405 5970,1405 6005,1405 3115,1665 4145,1665 4185,1665 3055,1685 3175,1685 5550,1690 5585,1690 5620,1690 5655,1690 5690,1690 6670,1690 6705,1690 6740,1690 6775,1690 6810,1690 4145,1705 4185,1705 5550,1725 5585,1725 5620,1725 5655,1725 5690,1725 6670,1725 6705,1725 6740,1725 6775,1725 6810,1725 3035,1745 3195,1745 4145,1745 4185,1745 4145,1785 4185,1785 3055,1805 3175,1805 3115,1825 3425,2225 6025,2235 6065,2235 6105,2235 6145,2235 6185,2235 6225,2235 6265,2235 6305,2235 6345,2235 6385,2235 6425,2235 6465,2235 6505,2235 6545,2235 6585,2235 6625,2235 6025,2275 6065,2275 6105,2275 6145,2275 6185,2275 6225,2275 6265,2275 6305,2275 6345,2275 6385,2275 6425,2275 6465,2275 6505,2275 6545,2275 6585,2275 6625,2275 6943.5,2295 6983.5,2295 7023.5,2295 7063.5,2295 7103.5,2295 7143.5,2295 7183.5,2295 7223.5,2295 7263.5,2295 7303.5,2295 7343.5,2295 6943.5,2335 6983.5,2335 7023.5,2335 7063.5,2335 7103.5,2335 7143.5,2335 7183.5,2335 7223.5,2335 7263.5,2335 7303.5,2335 7343.5,2335 5865,2370 5900,2370 5935,2370 5970,2370 6005,2370 6941.95,2373.93 6983.5,2375 7023.5,2375 7063.5,2375 7103.5,2375 7143.5,2375 7183.5,2375 7223.5,2375 7263.5,2375 7303.5,2375 7343.5,2375 5865,2405 5900,2405 5935,2405 5970,2405 6005,2405 6941.95,2413.93 6983.5,2415 7023.5,2415 7063.5,2415 7103.5,2415 7143.5,2415 7183.5,2415 7223.5,2415 7263.5,2415 7303.5,2415 7343.5,2415 6185,2425 6225,2425 6265,2425 6385,2425 6425,2425 6465,2425 6185,2465 6225,2465 6265,2465 6385,2465 6425,2465 6465,2465 7105,2465 7145,2465 7185,2465 6185,2505 6225,2505 6265,2505 6385,2505 6425,2505 6465,2505 7105,2505 7145,2505 7185,2505 6185,2545 6225,2545 6265,2545 6385,2545 6425,2545 6465,2545 7105,2545 7145,2545 7185,2545 6745,2555 6785,2555 6825,2555 3865.94,2565.63 3905.32,2565.63 3944.69,2565.63 3984.06,2565.63 3115,2585 6185,2585 6225,2585 6265,2585 6385,2585 6425,2585 6465,2585 7105,2585 7145,2585 7185,2585 3055,2605 3175,2605 3865.94,2605 3905.32,2605 3944.69,2605 3984.06,2605 3865.94,2644.37 3905.32,2644.37 3944.69,2644.37 3984.06,2644.37 3035,2665 3195,2665 3055,2725 3175,2725 3115,2745 5865,2810 5900,2810 5935,2810 5970,2810 6005,2810 4975,2825 5015,2825 5055,2825 5095,2825 5865,2845 5900,2845 5935,2845 5970,2845 6005,2845 4975,2865 5015,2865 5055,2865 5095,2865 2365,4245 2365,4330 2365,4430 1350,4505 2365,4505 2685,4505 2720,4505 2755,4505 2790,4505 2825,4505 2165,4530 2365,4605 2365,4680 2365,4760 1905,4805 2365,6765 2365,6850 2365,6950 1350,7025 2365,7025 2685,7025 2720,7025 2755,7025 2790,7025 2825,7025 2165,7050 2365,7125 2365,7200 2365,7280 1905,7325
HO-1: D19.1 R95.1 U11.19 | length 312.8
  Top w15: U11.19@4015.93,2487.5 U11.19@4014.57,2488.86 4014.57,2457.78 4027.35,2445 4095,2445 4145,2495 R95.1@4193.5,2495
  Top w20: D19.1@4181.69,2425 4181.69,2452.19 4193.5,2464 R95.1@4193.5,2495
HO-2: D24.1 R104.1 U12.19 | length 316.4
  Top w15: U12.19@4014.57,748.86 4014.57,715.43 4035,695 4095,695 4145,745 R104.1@4193.5,745
  Top w20: D24.1@4181.69,675 4181.69,702.19 4193.5,714 R104.1@4193.5,745
IN_L1: J3.1 J5_1.3 R20_1.1 | length 1929
  Inner Top w15: v1(215,4205) 215,4385 265,4435 265,5119.17 J5_1.3@570.83,5425 570.83,5789.17 515,5845 J3.1@515,5905
  Bottom w15: R20_1.1@215,4146.5 v1(215,4205)
IN_L2: J3.2 J5_2.3 R20_2.1 | length 2565.3
  Inner Top w15: J3.2@515,6005 515,6055 475,6095 155,6095 85,6165 85,6595 v1(215,6725) 215,6905 265,6955 265,7639.17 J5_2.3@570.83,7945
  Bottom w15: R20_2.1@215,6666.5 v1(215,6725)
IN_R1: J1.1 J8_1.3 R37_1.1 | length 1920
  Inner Top w15: v1(325,4205) 325,4379.17 J8_1.3@570.83,4625 715,4769.17 J1.1@715,5905
  Bottom w15: R37_1.1@325,4146.5 v1(325,4205)
IN_R2: J1.2 J8_2.3 R37_2.1 | length 1920.4
  Inner Top w15: J8_2.3@570.83,7145 325,6899.17 v1(325,6725) 130,6530 130,6177.99 167.99,6140 675,6140 715,6100 J1.2@715,6005
  Bottom w15: R37_2.1@325,6666.5 v1(325,6725)
INPUT_A_1: C21_1.1 R19_1.2 U8_1.5 | length 690.1
  Top w15: R19_1.2@1686.5,4525 v1(1740,4525) C21_1.1@1793.5,4525
  Inner Top w15: v1(1740,4525) 1780,4485 1953.7,4485 v1(2135,4303.7)
  Bottom w15: v1(2135,4303.7) 2173.8,4342.5 U8_1.5@2215.39,4342.5
INPUT_A_2: C21_2.1 R19_2.2 U8_2.5 | length 690.1
  Top w15: R19_2.2@1686.5,7045 v1(1740,7045) C21_2.1@1793.5,7045
  Inner Top w15: v1(1740,7045) 1780,7005 1953.7,7005 v1(2135,6823.7)
  Bottom w15: v1(2135,6823.7) 2173.8,6862.5 U8_2.5@2215.39,6862.5
INPUT_B_1: C28_1.1 R26_1.2 U8_1.6 | length 696.4
  Top w15: R26_1.2@1686.5,4605 v1(1740,4605) C28_1.1@1793.5,4605
  Inner Top w15: v1(1740,4605) 1780,4565 1918.7,4565 v1(2135,4348.7)
  Bottom w15: v1(2135,4348.7) 2153.8,4367.5 U8_1.6@2215.39,4367.5
INPUT_B_2: C28_2.1 R26_2.2 U8_2.6 | length 696.4
  Top w15: R26_2.2@1686.5,7125 v1(1740,7125) C28_2.1@1793.5,7125
  Inner Top w15: v1(1740,7125) 1780,7085 1918.7,7085 v1(2135,6868.7)
  Bottom w15: v1(2135,6868.7) 2153.8,6887.5 U8_2.6@2215.39,6887.5
INPUT_C_1: C40_1.1 R42_1.2 U8_1.16 | length 626.9
  Top w15: R42_1.2@1686.5,4725 v1(1740,4725) C40_1.1@1793.5,4725
  Inner Top w15: v1(1740,4725) 1780,4685 1925,4685 1971.3,4638.7 v1(2135,4638.7)
  Bottom w15: v1(2135,4638.7) 2156.2,4617.5 U8_1.16@2215.39,4617.5
INPUT_C_2: C40_2.1 R42_2.2 U8_2.16 | length 626.9
  Top w15: R42_2.2@1686.5,7245 v1(1740,7245) C40_2.1@1793.5,7245
  Inner Top w15: v1(1740,7245) 1780,7205 1925,7205 1971.3,7158.7 v1(2135,7158.7)
  Bottom w15: v1(2135,7158.7) 2156.2,7137.5 U8_2.16@2215.39,7137.5
INPUT_D_1: C37_1.1 R36_1.2 U8_1.17 | length 651
  Top w15: R36_1.2@1686.5,4805 v1(1740,4805) C37_1.1@1793.5,4805
  Inner Top w15: v1(1740,4805) 1780,4765 1925,4765 2006.3,4683.7 v1@2135,4683.7
  Bottom w15: v1(2135,4685) 2176.2,4643.8 2176.2,4642.5 U8_1.17@2215.39,4642.5
INPUT_D_2: C37_2.1 R36_2.2 U8_2.17 | length 651
  Top w15: R36_2.2@1686.5,7325 v1(1740,7325) C37_2.1@1793.5,7325
  Inner Top w15: v1(1740,7325) 1780,7285 1925,7285 2006.3,7203.7 v1@2135,7203.7
  Bottom w15: v1(2135,7205) 2176.2,7163.8 2176.2,7162.5 U8_2.17@2215.39,7162.5
LO-1: D17.1 D18.1 R93.1 R94.1 U11.16 | length 397.9
  Top w15: R93.1@3925,2336.5 3925,2435 3937.48,2447.48 U11.16@3937.48,2498.23
  Top w20: R94.1@3705,2336.5 3736,2336.5 3747.81,2348.31 D18.1@3775,2348.31 D17.1@3855,2348.31 3872.19,2348.31 3885.5,2335 3887,2336.5 R93.1@3925,2336.5
LO-2: D22.1 D23.1 R102.1 R103.1 U12.16 | length 397.4
  Top w15: R103.1@3925,586.5 3925,685 3937.8,697.8 U12.16@3937.8,748.86
  Top w20: R102.1@3705,586.5 3736,586.5 3747.81,598.31 D22.1@3775,598.31 D23.1@3855,598.31 3882.19,598.31 3894,586.5 R103.1@3925,586.5
NetC3_1: C3.1 D3.1 L1.1 U2.6
NetC3_2: C3.2 U2.1
NetC5_1: C5.1 C7.2 L1.2 L2.1
NetC8_1: C8.1 R9.1 R11.2 | length 160
  Top w15: R11.2@1405,453.5 R9.1@1565,453.5
NetC8_2: C8.2 R10.2 R11.1 U2.3 | length 255.4
  Top w15: R10.2@1325,516.5 C8.2@1485,516.5 ; U2.3@1402.4,617.76 1402.4,524.76 R11.1@1404.13,523.03
NetC9_1: C9.1 D8.1 L3.1 U3.6
NetC9_2: C9.2 U3.1
NetC10_2: C10.2 C12.1 D8.2 L4.1 U3.2
  other v1: 2010,560 2045,560 2110,785 2110,825 2110,865
NetC16_1: C16.1 U4.4
NetC17_1: C17.1 R17.2 R18.2 | length 172
  Top w15: R18.2@2005,443.5 C17.1@2085,443.5 2126.5,443.5 2135,435 R17.2@2173.5,435
NetC17_2: C17.2 R16.1 R18.1 U3.3 | length 274.4
  Top w15: R18.1@2005,506.5 C17.2@2085,506.5 ; C17.2@2082.4,509.09 C17.2@2085,506.5 ; C17.2@2082.4,519.09 U3.3@2082.4,617.76 ; R16.1@2173.5,515 2135,515 2126.5,506.5 C17.2@2085,506.5
NetC18_1_1: C18_1.1 R19_1.1 | length 847
  Top w15: v1(1575,4525) 1622.2,4525 R19_1.1@1623.5,4523.7
  Inner Top w15: C18_1.1@1483.43,3765 1575,3856.57 v1(1575,4525)
NetC18_1_2: C18_1.2 J6_1.2 R27_1.1 | length 549.1
  Inner Top w15: C18_1.2@1286.57,3765 1385,3863.43 J6_1.2@1385,4045 1385,4140 v1(1450,4205)
  Bottom w15: R27_1.1@1408.62,4205 v1(1450,4205)
NetC18_2_1: C18_2.1 R19_2.1 | length 847
  Top w15: v1(1575,7045) 1622.2,7045 R19_2.1@1623.5,7043.7
  Inner Top w15: C18_2.1@1483.43,6285 1575,6376.57 v1(1575,7045)
NetC18_2_2: C18_2.2 J6_2.2 R27_2.1 | length 549.1
  Inner Top w15: C18_2.2@1286.57,6285 1385,6383.43 J6_2.2@1385,6565 1385,6660 v1(1450,6725)
  Bottom w15: R27_2.1@1408.62,6725 v1(1450,6725)
NetC20_1_1: C20_1.1 C25_1.2 R21_1.2 U6_1.1 | length 388.2
  Inner Top w15: C25_1.2@1286.57,4325 1346.57,4265 v1(1450,4265)
  Bottom w15: U6_1.1@1423.39,4417.4 1423.39,4373.39 1408.62,4358.62 R21_1.2@1408.62,4325 C20_1.1@1408.62,4265 v1(1450,4265)
NetC20_1_2: C20_1.2 R21_1.1 R27_1.2 U6_1.2 | length 227.5
  Bottom w15: R27_1.2@1361.38,4205 R21_1.1@1361.38,4325 1361.38,4351.38 1397.8,4387.8 U6_1.2@1397.8,4417.4
NetC20_2_1: C20_2.1 C25_2.2 R21_2.2 U6_2.1 | length 388.2
  Inner Top w15: C25_2.2@1286.57,6845 1346.57,6785 v1(1450,6785)
  Bottom w15: U6_2.1@1423.39,6937.4 1423.39,6893.39 1408.62,6878.62 R21_2.2@1408.62,6845 C20_2.1@1408.62,6785 v1(1450,6785)
NetC20_2_2: C20_2.2 R21_2.1 R27_2.2 U6_2.2 | length 227.5
  Bottom w15: R27_2.2@1361.38,6725 R21_2.1@1361.38,6845 1361.38,6871.38 1397.8,6907.8 U6_2.2@1397.8,6937.4
NetC22_1_1: C22_1.1 R24_1.2 U5_1.3 | length 497.9
  Top w15: U5_1.3@1010,3837.72 1010,3780 v1(1035,3755)
  Inner Top w15: C22_1.1@713.43,3765 762.64,3765 772.64,3755 v1(1035,3755)
  Bottom w15: C22_1.1@713.43,3765 713.43,3841.93 R24_1.2@715,3843.5
NetC22_1_2: C22_1.2 R29_1.2 | length 327.9
  Inner Top w15: R29_1.2@221.85,3845 271.85,3795 486.57,3795 C22_1.2@516.57,3765
NetC22_2_1: C22_2.1 R24_2.2 U5_2.3 | length 497.9
  Top w15: U5_2.3@1010,6357.72 1010,6300 v1(1035,6275)
  Inner Top w15: C22_2.1@713.43,6285 762.64,6285 772.64,6275 v1(1035,6275)
  Bottom w15: C22_2.1@713.43,6285 713.43,6361.93 R24_2.2@715,6363.5
NetC22_2_2: C22_2.2 R29_2.2 | length 327.9
  Inner Top w15: R29_2.2@221.85,6365 271.85,6315 486.57,6315 C22_2.2@516.57,6285
NetC24_1_1: C24_1.1 R20_1.2 R29_1.3 | length 453.9
  Inner Bottom w15: v1(180,4010) 146.02,3976.02 145,3976.02 145,3825 221.85,3748.15 R29_1.3@221.85,3746.57
  Bottom w15: C24_1.1@145,4083.5 180,4083.5 ; v1(180,4010) 180,4083.5 ; R20_1.2@215,4083.5 180,4083.5
NetC24_2_1: C24_2.1 R20_2.2 R29_2.3 | length 453.9
  Inner Bottom w15: v1(180,6530) 146.02,6496.02 145,6496.02 145,6345 221.85,6268.15 R29_2.3@221.85,6266.57
  Bottom w15: C24_2.1@145,6603.5 180,6603.5 ; v1(180,6530) 180,6603.5 ; R20_2.2@215,6603.5 180,6603.5
NetC25_1_1: C25_1.1 R26_1.1 | length 367
  Top w15: v1(1575,4605) 1622.2,4605 R26_1.1@1623.5,4603.7
  Inner Top w15: C25_1.1@1483.43,4325 1483.43,4513.43 v1(1575,4605)
NetC25_2_1: C25_2.1 R26_2.1 | length 367
  Top w15: v1(1575,7125) 1622.2,7125 R26_2.1@1623.5,7123.7
  Inner Top w15: C25_2.1@1483.43,6845 1483.43,7033.43 v1(1575,7125)
NetC27_1_1: C27_1.1 J6_1.3 J7_1.3 R22_1.2 U7_1.7 | length 2064.4
  Top w15: C27_1.1@886.57,5335 886.57,5183.43 906.5,5163.5 R22_1.2@935,5163.5 935,5125 960,5100 U7_1.7@960,5072.28
  Inner Top w15: C27_1.1@886.57,5335 946.57,5275 1175,5275 J7_1.3@1485,4965
  Inner Bottom w15: J6_1.3@1485,4045 1385,4145 1385,4855 1385,4865 J7_1.3@1485,4965
NetC27_1_2: C27_1.2 R34_1.2 U7_1.6 | length 309.8
  Top w15: U7_1.6@1010,5072.28 1010,5100 1035,5125 R34_1.2@1035,5163.5 1063.5,5163.5 1083.43,5183.43 C27_1.2@1083.43,5335
NetC27_2_1: C27_2.1 J6_2.3 J7_2.3 R22_2.2 U7_2.7 | length 2064.4
  Top w15: C27_2.1@886.57,7855 886.57,7703.43 906.5,7683.5 R22_2.2@935,7683.5 935,7645 960,7620 U7_2.7@960,7592.28
  Inner Top w15: C27_2.1@886.57,7855 946.57,7795 1175,7795 J7_2.3@1485,7485
  Inner Bottom w15: J6_2.3@1485,6565 1385,6665 1385,7375 1385,7385 J7_2.3@1485,7485
NetC27_2_2: C27_2.2 R34_2.2 U7_2.6 | length 309.8
  Top w15: U7_2.6@1010,7592.28 1010,7620 1035,7645 R34_2.2@1035,7683.5 1063.5,7683.5 1083.43,7703.43 C27_2.2@1083.43,7855
NetC31_1_1: C31_1.1 C32_1.2 R38_1.2 U6_1.7 | length 844.7
  Inner Top w15: C32_1.2@1286.57,5245 1545,4986.57 1545,4840 v1(1450,4745)
  Bottom w15: U6_1.7@1397.8,4592.6 1397.8,4637.8 1408.62,4648.62 R38_1.2@1408.62,4685 C31_1.1@1408.62,4745 v1(1450,4745)
NetC31_1_2: C31_1.2 R38_1.1 R39_1.2 U6_1.6 | length 216.9
  Bottom w15: R39_1.2@1361.38,4805 R38_1.1@1361.38,4685 1361.38,4648.62 1372.2,4637.8 U6_1.6@1372.2,4592.6
NetC31_2_1: C31_2.1 C32_2.2 R38_2.2 U6_2.7 | length 844.7
  Inner Top w15: C32_2.2@1286.57,7765 1545,7506.57 1545,7360 v1(1450,7265)
  Bottom w15: U6_2.7@1397.8,7112.6 1397.8,7157.8 1408.62,7168.62 R38_2.2@1408.62,7205 C31_2.1@1408.62,7265 v1(1450,7265)
NetC31_2_2: C31_2.2 R38_2.1 R39_2.2 U6_2.6 | length 216.9
  Bottom w15: R39_2.2@1361.38,7325 R38_2.1@1361.38,7205 1361.38,7168.62 1372.2,7157.8 U6_2.6@1372.2,7112.6
NetC32_1_1: C32_1.1 R36_1.1 | length 527
  Top w15: v1(1575,4805) 1622.2,4805 R36_1.1@1623.5,4803.7
  Inner Top w15: C32_1.1@1483.43,5245 1575,5153.43 v1(1575,4805)
NetC32_2_1: C32_2.1 R36_2.1 | length 527
  Top w15: v1(1575,7325) 1622.2,7325 R36_2.1@1623.5,7323.7
  Inner Top w15: C32_2.1@1483.43,7765 1575,7673.43 v1(1575,7325)
NetC33_1_1: C33_1.1 C34_1.1 R22_1.1 R34_1.1 R35_1.2 | length 1068.1
  Top w15: C34_1.1@886.57,4425 C33_1.1@886.57,4555 915,4555 936.5,4576.5 R35_1.2@936.5,4665 ; R22_1.1@945,5226.5 R34_1.1@1025,5226.5
  Inner Top w15: C33_1.1@886.57,4555 985,4653.43 v1(985,5225)
NetC33_2_1: C33_2.1 C34_2.1 R22_2.1 R34_2.1 R35_2.2 | length 1068.1
  Top w15: C34_2.1@886.57,6945 C33_2.1@886.57,7075 915,7075 936.5,7096.5 R35_2.2@936.5,7185 ; R22_2.1@945,7746.5 R34_2.1@1025,7746.5
  Inner Top w15: C33_2.1@886.57,7075 985,7173.43 v1(985,7745)
NetC35_1_1: C35_1.1 R41_1.2 U5_1.5 | length 576.6
  Top w15: U5_1.5@1062.72,4055 U5_1.5@1060,4052.28 1060,4110 v1(1085,4135)
  Inner Top w15: C35_1.1@713.43,4125 795,4125 825,4095 1045,4095 v1(1085,4135)
  Bottom w15: C35_1.1@713.43,4125 713.43,4048.07 R41_1.2@715,4046.5
NetC35_1_2: C35_1.2 R29_1.2' | length 452.9
  Inner Top w15: R29_1.2'@320.28,3845 415,3845 435,3865 435,4105 455,4125 C35_1.2@516.57,4125
NetC35_2_1: C35_2.1 R41_2.2 U5_2.5 | length 576.6
  Top w15: U5_2.5@1062.72,6575 U5_2.5@1060,6572.28 1060,6630 v1(1085,6655)
  Inner Top w15: C35_2.1@713.43,6645 795,6645 825,6615 1045,6615 v1(1085,6655)
  Bottom w15: C35_2.1@713.43,6645 713.43,6568.07 R41_2.2@715,6566.5
NetC35_2_2: C35_2.2 R29_2.2' | length 452.9
  Inner Top w15: R29_2.2'@320.28,6365 415,6365 435,6385 435,6625 455,6645 C35_2.2@516.57,6645
NetC38_1_1: C38_1.1 R29_1.3' R37_1.2 | length 452.4
  Inner Bottom w15: R29_1.3'@320.28,3746.57 395,3821.3 395,3975 v1(360,4010)
  Bottom w15: R37_1.2@325,4083.5 360,4083.5 ; v1(360,4010) 360,4083.5 ; C38_1.1@395,4083.5 360,4083.5
NetC38_2_1: C38_2.1 R29_2.3' R37_2.2 | length 452.4
  Inner Bottom w15: R29_2.3'@320.28,6266.57 395,6341.3 395,6495 v1(360,6530)
  Bottom w15: R37_2.2@325,6603.5 360,6603.5 ; v1(360,6530) 360,6603.5 ; C38_2.1@395,6603.5 360,6603.5
NetC39_1_1: C39_1.1 R42_1.1 | length 158.8
  Top w15: C39_1.1@1483.43,4685 C39_1.1@1485,4685 ; v1(1575,4725) 1622.2,4725 R42_1.1@1623.5,4723.7
  Inner Top w15: C39_1.1@1483.43,4685 1535,4685 v1(1575,4725)
NetC39_1_2: C39_1.2 J7_1.2 R39_1.1 | length 449.1
  Inner Top w15: C39_1.2@1286.57,4685 1286.57,4771.57 1385,4870 ; J7_1.2@1385,4965 1385,4870 ; v1(1450,4805) 1385,4870
  Bottom w15: R39_1.1@1408.62,4805 v1@1445,4805
NetC39_2_1: C39_2.1 R42_2.1 | length 158.8
  Top w15: C39_2.1@1483.43,7205 C39_2.1@1485,7205 ; v1(1575,7245) 1622.2,7245 R42_2.1@1623.5,7243.7
  Inner Top w15: C39_2.1@1483.43,7205 1535,7205 v1(1575,7245)
NetC39_2_2: C39_2.2 J7_2.2 R39_2.1 | length 449.1
  Inner Top w15: C39_2.2@1286.57,7205 1286.57,7291.57 1385,7390 ; J7_2.2@1385,7485 1385,7390 ; v1(1450,7325) 1385,7390
  Bottom w15: R39_2.1@1408.62,7325 v1@1445,7325
NetC41_1_1: C41_1.1 C56_1.1 C57_1.1 J9_1.1 J9_1.2 J10_1.1 L5_1.2 | length 163.8
  Bottom w25: C57_1.1@4675,3513.5 C41_1.1@4755,3513.5 C56_1.1@4755,3429.72
  other v1: 4265,3355 4305,3355 4265,3395 4305,3395 4265,3435 4305,3435 4265,3475 4305,3475 4265,3515 4305,3515 7105,3525 7145,3525 7625,3525 7665,3525 7105,3565 7145,3565 7625,3565 7665,3565 4035,3595 4075,3595 4115,3595 4155,3595 4195,3595 7105,3605 7145,3605 7625,3605 7665,3605 4035,3635 4075,3635 4115,3635 4155,3635 4195,3635 7105,3645 7145,3645 7625,3645 7665,3645 7105,3685 7145,3685 7625,3685 7665,3685
NetC41_1_2: C41_1.2 R45_1.2 | length 80
  Bottom w25: C41_1.2@4755,3576.5 R45_1.2@4835,3576.5
NetC41_2_1: C41_2.1 C56_2.1 C57_2.1 J9_2.1 J9_2.2 J10_2.1 L5_2.2 | length 163.8
  Bottom w25: C57_2.1@4675,6033.5 C41_2.1@4755,6033.5 C56_2.1@4755,5949.72
  other v1: 4265,5875 4305,5875 4265,5915 4305,5915 4265,5955 4305,5955 4265,5995 4305,5995 4265,6035 4305,6035 7105,6045 7145,6045 7625,6045 7665,6045 7105,6085 7145,6085 7625,6085 7665,6085 4035,6115 4075,6115 4115,6115 4155,6115 4195,6115 7105,6125 7145,6125 7625,6125 7665,6125 4035,6155 4075,6155 4115,6155 4155,6155 4195,6155 7105,6165 7145,6165 7625,6165 7665,6165 7105,6205 7145,6205 7625,6205 7665,6205
NetC41_2_2: C41_2.2 R45_2.2 | length 80
  Bottom w25: C41_2.2@4755,6096.5 R45_2.2@4835,6096.5
NetC54_1_1: C54_1.1 U8_1.43 | length 268.5
  Top w15: v1(2545,4120) 2545,4185 v1(2585,4225)
  Bottom w15: U8_1.43@2514.61,4267.5 2542.5,4267.5 v1(2585,4225) ; C54_1.1@2523.5,4070 2523.5,4098.5 v1(2545,4120)
NetC54_1_2: C54_1.2 L6_1.2 U8_1.35 | length 576.3
  Top w15: v1(2585,4028.7) 2515,4098.7 2515,4448.7 2535,4468.7 v1(2585,4468.7)
  Bottom w15: v1(2585,4028.7) 2585,4073.5 C54_1.2@2586.5,4075 ; C54_1.2@2595,4080.2 C54_1.2@2596.5,4078.7
  other v1: 3655,4015 3695,4015 3655,4055 3695,4055 3655,4095 3695,4095 3655,4135 3695,4135 5315,4135 5355,4135 5395,4135 5435,4135 5475,4135 3655,4175 3695,4175 5315,4175 5355,4175 5395,4175 5435,4175 5475,4175 3655,4215 3695,4215 3655,4255 3695,4255 5205,4255 5245,4255 3655,4295 3695,4295 5205,4295 5245,4295 3655,4335 3695,4335 5205,4335 5245,4335 3655,4375 3695,4375 5205,4375 5245,4375 5205,4415 5245,4415 2615,4470
NetC54_2_1: C54_2.1 U8_2.43 | length 268.5
  Top w15: v1(2545,6640) 2545,6705 v1(2585,6745)
  Bottom w15: U8_2.43@2514.61,6787.5 2542.5,6787.5 v1(2585,6745) ; C54_2.1@2523.5,6590 2523.5,6618.5 v1(2545,6640)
